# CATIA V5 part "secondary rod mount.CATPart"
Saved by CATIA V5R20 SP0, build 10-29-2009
Part number: secondary rod mount
Source: Unknown
Bounding box of the stored display mesh (mm): x 0 to 50, y -10 to 58.3, z -46 to 0
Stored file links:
  C:\Users\Ikarus\OneDrive - FH JOANNEUM\BAC - Arbeit 1\CAD Modell\CAD-Modell-Step files\rod mount\secondary\secondary rod mount.CATPart
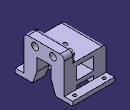
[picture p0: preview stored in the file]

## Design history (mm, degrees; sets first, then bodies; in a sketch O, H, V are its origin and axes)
Body1 (main body)
  Solid1 "Hauptkörper": solid without history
